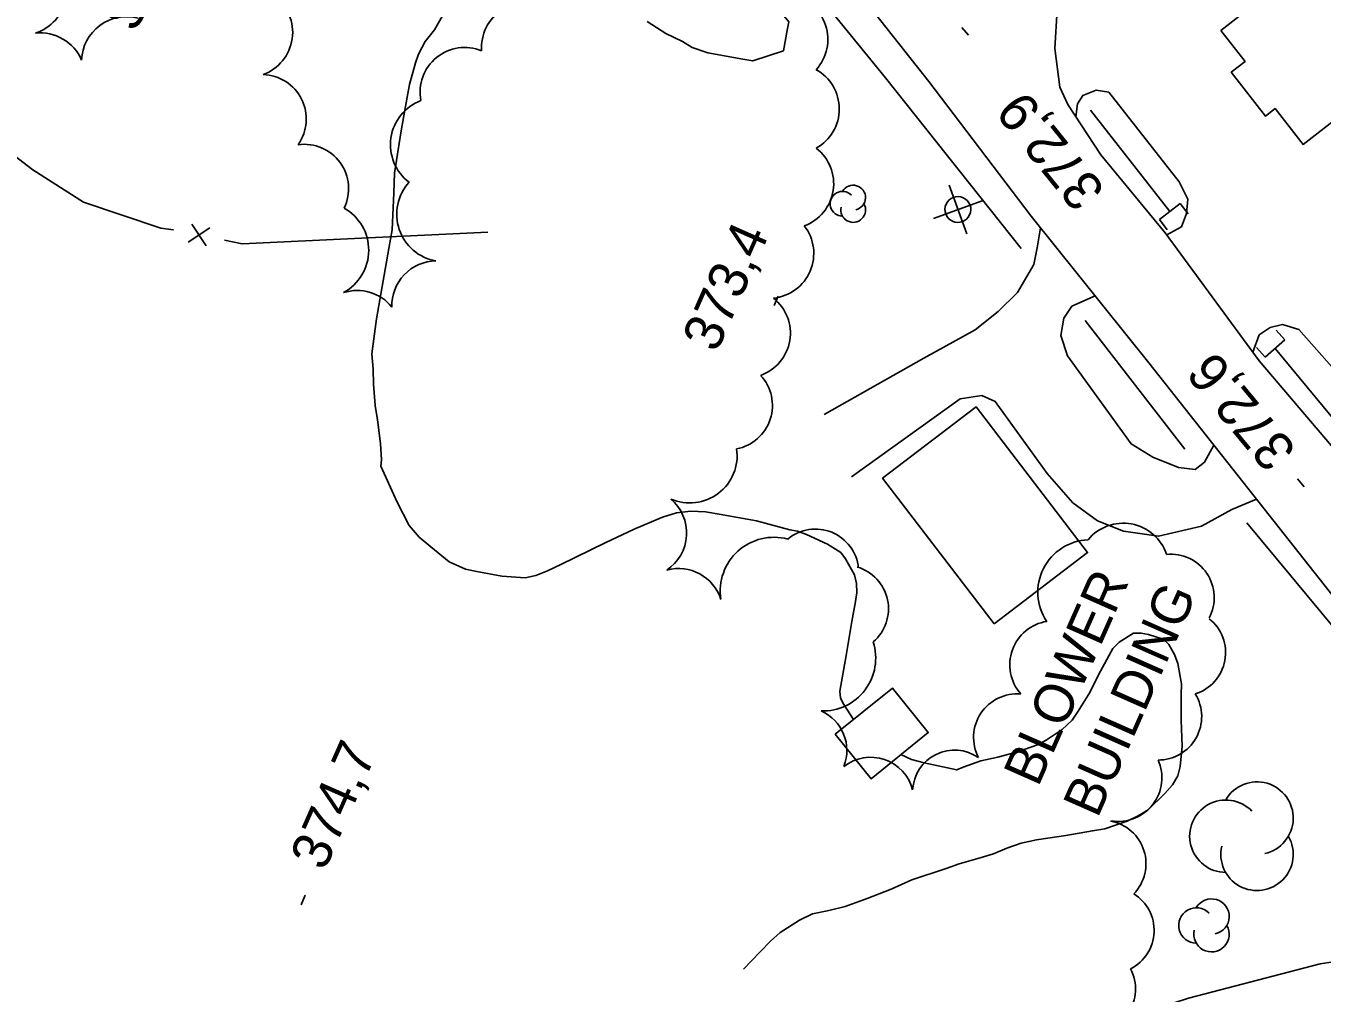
# Model space of a CAD drawing. Extents: x 287698 to 290158, y 5234163 to 5237182.
# Drawn here: x 288956.3 to 289056.1, y 5234872.4 to 5234946.9 of the extents above; entities that cross this region are included whole.
import ezdxf

# ---------------------------------------------------------------- set-up
doc = ezdxf.new("R2010")
doc.units = 0
for name, color, linetype in [('Niveau 19', 7, 'Continuous'), ('Niveau 2', 7, 'Continuous'), ('Niveau 21', 7, 'Continuous'), ('Niveau 26', 7, 'Continuous'), ('Niveau 3', 7, 'Continuous'), ('Niveau 31', 7, 'Continuous'), ('Niveau 36', 7, 'Continuous'), ('Niveau 37', 7, 'Continuous'), ('Niveau 4', 7, 'Continuous'), ('Niveau 44', 7, 'Continuous')]:
    doc.layers.add(name, color=color, linetype=linetype)

msp = doc.modelspace()

# ---------------------------------------------------------------- linework, layer by layer
at = {"layer": 'Niveau 19'}
for points in [[(289044.09, 5234930.8), (289045.22, 5234931.44), (289045.62, 5234932.45), (289045.72, 5234933.57), (289045.06, 5234934.9), (289039.63, 5234941.79), (289038.67, 5234941.96), (289037.64, 5234941.55), (289037.22, 5234940.89), (289037.09, 5234939.91)], [(289017.72, 5234916.99), (289025.38, 5234921.31), (289029.35, 5234923.51), (289031.12, 5234924.92), (289032.59, 5234926.37), (289033.87, 5234928.52), (289034.12, 5234929.82), (289034.37, 5234931.36)], [(289038.58, 5234926.11), (289036.79, 5234925.31), (289036.17, 5234924.4), (289035.93, 5234923.06), (289036.44, 5234921.49), (289041.34, 5234914.71), (289043.01, 5234913.69), (289045, 5234912.89), (289046.28, 5234912.75), (289047, 5234913.31), (289047.72, 5234914.61)], [(289059.69, 5234911.09), (289061.21, 5234912.33), (289061.52, 5234913.44), (289061.49, 5234914.76), (289060.94, 5234915.98), (289054.27, 5234923.53), (289053.01, 5234923.91), (289052.06, 5234923.68), (289051.2, 5234923.1), (289050.72, 5234921.79)], [(289051, 5234910.45), (289049.1, 5234909.65), (289046.78, 5234908.37), (289043.46, 5234907.6), (289040.75, 5234908), (289038.75, 5234908.79), (289036.87, 5234910.18), (289034.89, 5234912.44), (289030.89, 5234917.98), (289029.86, 5234918.45), (289028.19, 5234918.19), (289019.81, 5234912.17)], [(289039, 5234869.83), (289045.76, 5234872.04), (289055.91, 5234874.68), (289062.92, 5234875.75), (289066.89, 5234876.7), (289069.42, 5234877.47), (289071.11, 5234878.17), (289072.37, 5234879.23), (289073.22, 5234880.46), (289074.14, 5234881.87)]]:
    msp.add_lwpolyline(points, dxfattribs=at)
at = {"layer": 'Niveau 2'}
for points in [[(288997.13, 5234971.38), (288998.91, 5234968.79), (288999.04, 5234968.28), (288999.36, 5234967.88), (288999.63, 5234967.22), (289000.2, 5234966.21), (289000.98, 5234964.73), (289001.83, 5234963.48), (289002.39, 5234962.51), (289003.09, 5234961.52), (289004, 5234960.46), (289005.87, 5234958.04), (289007.66, 5234955.86), (289009.68, 5234953.37), (289011.15, 5234951.48), (289011.94, 5234950.63), (289014.15, 5234948.23), (289014.99, 5234947.21), (289014.9, 5234946.7), (289014.59, 5234944.99)], [(288988.34, 5234947.67), (288987.71, 5234946.6), (288987, 5234945.69), (288986.48, 5234944.72), (288986.27, 5234944.07), (288985.79, 5234942.39), (288985.62, 5234941.42), (288985.15, 5234938.81), (288984.64, 5234935.56), (288984.58, 5234934.05), (288984.46, 5234931.19), (288984.21, 5234929.75), (288983.77, 5234927.27), (288983.25, 5234924.34), (288982.9, 5234921.66), (288983, 5234920.48), (288983.02, 5234919.32), (288983.15, 5234917.67), (288983.34, 5234916.56), (288983.57, 5234914.75), (288983.65, 5234913.48), (288983.59, 5234913.01)], [(289014.59, 5234944.99), (289012.22, 5234944.21), (289011.46, 5234944.34), (289008.76, 5234944.82), (289007.55, 5234945.23), (289006.82, 5234945.71), (289005.53, 5234946.32), (289004.08, 5234947.23)], [(288983.59, 5234913.01), (288984.85, 5234910.24), (288985.77, 5234908.44), (288986.54, 5234907.53), (288987.45, 5234906.8), (288988.85, 5234905.62), (288990.11, 5234905.07), (288990.99, 5234904.88), (288992.9, 5234904.54), (288994.69, 5234904.41), (288995.51, 5234904.59), (288996.43, 5234904.95), (288997.45, 5234905.44), (289000.85, 5234907.1), (289003.08, 5234908.15), (289005.26, 5234909.08), (289006.35, 5234909.4), (289007.45, 5234909.53), (289008.58, 5234909.47), (289009.64, 5234909.3), (289012.5, 5234908.8), (289015.08, 5234908.1), (289015.67, 5234908), (289016.37, 5234907.73), (289017.97, 5234907), (289018.99, 5234906.36), (289019.37, 5234905.86), (289020.05, 5234904.63), (289020.22, 5234903.97), (289020.24, 5234903.27), (289020.14, 5234902.58), (289019.86, 5234901.04), (289019.4, 5234898.42), (289018.92, 5234895.67), (289018.98, 5234895.13), (289019.22, 5234894.64), (289019.98, 5234893.49)], [(289025.42, 5234890.15), (289027.92, 5234889.61), (289028.41, 5234889.83), (289029.79, 5234890.3), (289031.1, 5234890.59), (289032.59, 5234891), (289034.15, 5234891.54), (289034.81, 5234891.91), (289036.04, 5234892.71), (289036.8, 5234893.45), (289037.27, 5234894.14), (289038.17, 5234895.56), (289038.84, 5234896.93), (289039.94, 5234898.95), (289040.42, 5234899.45), (289041.52, 5234900.15), (289042.11, 5234900.15), (289042.7, 5234900.04), (289043.81, 5234899.67), (289044.25, 5234899.26), (289044.7, 5234898.49), (289044.94, 5234897.8), (289045.23, 5234896.23), (289045.19, 5234895.4), (289045.21, 5234893.45), (289045.28, 5234891.44), (289045.13, 5234889.87), (289044.94, 5234889.15), (289044.54, 5234888.47), (289043.95, 5234887.8), (289042.67, 5234886.54), (289041.9, 5234886.07), (289041.04, 5234885.67), (289039.33, 5234885.08), (289038.37, 5234884.93), (289036.33, 5234884.57), (289034.06, 5234884.22), (289032.88, 5234883.97), (289031.77, 5234883.59), (289030.76, 5234883.16), (289029.73, 5234882.83), (289028.11, 5234882.39), (289027.11, 5234882.02)], [(289023.63, 5234890.79), (289024.43, 5234890.41), (289025.42, 5234890.15)], [(289027.11, 5234882.02), (289024.46, 5234881.14), (289022.87, 5234880.43), (289021.02, 5234879.7), (289019.33, 5234879.1), (289018.07, 5234878.78), (289016.81, 5234878.53), (289015.81, 5234878.04), (289014.34, 5234877.08), (289013.59, 5234876.42), (289012.78, 5234875.61), (289011.52, 5234874.27)]]:
    msp.add_lwpolyline(points, dxfattribs=at)
at = {"layer": 'Niveau 21'}
for points in [[(289065.93, 5234814.28), (289080.43, 5234820.36), (289085.56, 5234822.15), (289095.57, 5234827.48), (289103.57, 5234831.83), (289105.46, 5234833.33), (289106.17, 5234834.93), (289106.24, 5234836.58), (289105.61, 5234838.24), (289104.03, 5234840.63), (289095.62, 5234852.75), (289088.9, 5234862.55), (289082.75, 5234870.74), (289074.14, 5234881.87), (289074.07, 5234881.96), (289067.25, 5234890.31), (289060.07, 5234898.99), (289052.35, 5234908.74), (289042.72, 5234920.95), (289033.65, 5234932.26), (289025.77, 5234942.63), (289016.04, 5234954.94)], [(289035.66, 5234948.13), (289035.47, 5234945.17), (289035.87, 5234942.18), (289036.47, 5234940.85), (289039.03, 5234936.97), (289043.97, 5234930.96), (289051.21, 5234921.12), (289059.26, 5234911.63), (289067.32, 5234901.46), (289070.83, 5234898.1), (289073.27, 5234896.43), (289076.14, 5234894.85), (289078.86, 5234894.47), (289081.5, 5234894.71), (289083.59, 5234895.4), (289086.13, 5234897.23), (289091.41, 5234902.88), (289091.45, 5234902.93), (289098.48, 5234911.99), (289103.98, 5234919.57), (289110.69, 5234928.93), (289116.61, 5234937.16), (289117.22, 5234937.97), (289124.9, 5234948.27)]]:
    msp.add_lwpolyline(points, dxfattribs=at)
at = {"layer": 'Niveau 26'}
for p, q in [((289043.53, 5234931.99), (289045.13, 5234933.22)), ((289045.13, 5234933.22), (289045.74, 5234932.43)), ((289043.53, 5234931.99), (289044.13, 5234931.2)), ((289053.19, 5234922.74), (289051.68, 5234921.39)), ((289053.19, 5234922.74), (289052.52, 5234923.48)), ((289051.68, 5234921.39), (289051.01, 5234922.14))]:
    msp.add_line(p, q, dxfattribs=at)
at = {"layer": 'Niveau 3'}
for p, q in [((289028.83, 5234946.19), (289028.31, 5234946.79)), ((289013.86, 5234925.37), (289014.18, 5234926.1)), ((289054.66, 5234911.41), (289054.15, 5234912.02)), ((288977.45, 5234879.23), (288977.77, 5234879.96))]:
    msp.add_line(p, q, dxfattribs=at)
at = {"layer": 'Niveau 31'}
for points in [[(289048.26, 5234946.55), (289054.75, 5234951.62), (289058.14, 5234947.28), (289060.76, 5234949.31), (289063.73, 5234945.5), (289060.76, 5234943.18), (289061.05, 5234942.81), (289054.59, 5234937.77), (289052.43, 5234940.54), (289051.69, 5234939.96), (289049.06, 5234943.33), (289050.12, 5234944.16)], [(289030.81, 5234900.85), (289022.22, 5234912.07), (289029.41, 5234917.57), (289038, 5234906.35)], [(289018.57, 5234892.35), (289022.97, 5234895.91), (289025.73, 5234892.49), (289021.33, 5234888.93)]]:
    msp.add_lwpolyline(points, close=True, dxfattribs=at)
at = {"layer": 'Niveau 36'}
for p, q in [((289028.7, 5234930.88), (289027.33, 5234934.63)), ((289029.89, 5234933.44), (289026.14, 5234932.07))]:
    msp.add_line(p, q, dxfattribs=at)
msp.add_ellipse((289028.012, 5234932.763), major_axis=(-0.907, 0.42), ratio=0.999982, dxfattribs=at)
at = {"layer": 'Niveau 37'}
for p, q in [((288948.69, 5234941.97), (288956.81, 5234935.83)), ((288970.14, 5234929.97), (288969.03, 5234931.63)), ((288968.76, 5234930.24), (288970.43, 5234931.36))]:
    msp.add_line(p, q, dxfattribs=at)
for points in [[(288956.81, 5234935.83), (288960.71, 5234933.32), (288966.65, 5234931.32), (288967.63, 5234931.19)], [(288971.55, 5234930.41), (288972.92, 5234930.13), (288991.82, 5234931.02)]]:
    msp.add_lwpolyline(points, dxfattribs=at)
at = {"layer": 'Niveau 4'}
for points in [[(288993.28, 5234980.88), (289004.62, 5234965.6), (289015.19, 5234951.84), (289022.45, 5234942.9), (289032.88, 5234929.75)], [(289038.21, 5234940.42), (289044.32, 5234932.6)], [(289037.82, 5234924.21), (289045.49, 5234914.31)], [(289052.44, 5234922.07), (289060.32, 5234912.54)], [(289050.26, 5234908.63), (289059.43, 5234897.61), (289072.56, 5234881.93)]]:
    msp.add_lwpolyline(points, dxfattribs=at)
at = {"layer": 'Niveau 44'}
for centre, radius, start, end in [((288987.977, 5234937.753), 3.645, 110.84077, 232.54268), ((288977.687, 5234934.365), 3.42, 334.14127, 97.77373), ((288988.474, 5234932.404), 3.661, 137.85158, 259.86713), ((289019.951, 5234933.682), 0.954, 282.26917, 149.72626), ((289019.131, 5234933.205), 0.954, 44.11537, 269.80396), ((289019.951, 5234932.728), 0.954, 166.93686, 29.62123), ((289013.461, 5234929.378), 3.457, 275.95745, 37.86942), ((289011.663, 5234923.242), 3.455, 289.74371, 51.36288), ((289017.039, 5234904.804), 3.349, 6.09813, 129.47002), ((289013.86, 5234903.381), 4.144, 75.33067, 188.76329), ((289038.196, 5234903.306), 4.027, 92.35548, 214.07732), ((289017.617, 5234898.216), 4.068, 268.21379, 17.80134), ((289043.438, 5234893.714), 3.344, 269.69203, 31.47496), ((289051.043, 5234885.898), 2.789, 282.26917, 149.72626), ((289048.645, 5234884.504), 2.789, 44.11537, 269.80396), ((289051.043, 5234883.11), 2.789, 166.93686, 29.62123), ((289039.821, 5234877.247), 3.302, 296.80527, 58.42284), ((289047.538, 5234878.317), 1.361, 282.26917, 149.72626), ((289046.368, 5234877.636), 1.361, 44.11537, 269.80396), ((289047.538, 5234876.956), 1.361, 166.93686, 29.62123), ((289038.294, 5234872.75), 3.391, 265.20123, 27.20434)]:
    msp.add_arc(centre, radius, start, end, dxfattribs=at)
for centre, major_axis, ratio, start_param, end_param in [((288955.929, 5234949.639), (1.757, 2.987), 0.999586, 3.984847, 6.137782), ((288973.333, 5234946.408), (0.494, 3.434), 0.999625, 3.634483, 5.790295), ((288994.764, 5234945.244), (-2.885, -1.845), 0.999862, 3.633416, 5.791362), ((289014.544, 5234945.854), (3.274, 1.111), 0.998925, 5.217696, 7.34218), ((288964.003, 5234944.16), (-2.373, -2.509), 0.999761, 3.6306, 5.438132), ((288957.371, 5234942.891), (-1.97, 2.856), 0.999759, 4.517673, 5.789132), ((288990.04, 5234941.816), (-2.65, -2.168), 0.999862, 3.634329, 5.790449), ((288974.424, 5234939.726), (-1.534, 3.063), 0.999985, 3.634366, 5.790412), ((289015.422, 5234940.507), (3.458, 0), 0.999731, 5.222352, 7.347329), ((289014.983, 5234934.751), (3.426, -0.535), 0.999978, 5.22288, 7.348687), ((288978.926, 5234929.629), (3.729, -0.029), 0.999981, 5.223602, 7.346186), ((288987.868, 5234925.372), (-1.597, -3.033), 0.999938, 3.637441, 5.232787), ((288981.773, 5234923.113), (2.472, 2.359), 0.999448, 6.196336, 7.404325), ((289010.33, 5234917.675), (3.241, -1.051), 0.999949, 5.217991, 7.343803), ((289007.371, 5234913.811), (1.633, -3.261), 0.999897, 5.406873, 7.532562), ((289003.704, 5234907.851), (3.352, 0.703), 0.999679, 5.092839, 6.947196), ((289040.74, 5234905.097), (0.64, 3.453), 0.99974, 5.218199, 7.3481), ((289044.397, 5234902.879), (0.903, 3.223), 0.99958, 4.497646, 6.654252), ((289006.507, 5234901.696), (-3.209, 1.197), 0.999938, 3.808434, 5.337363), ((289019.316, 5234902.013), (-0.699, 3.28), 0.999417, 3.637318, 5.78746), ((289035.405, 5234897.697), (-2.925, 1.727), 0.999881, 5.407038, 7.535866), ((289045.284, 5234898.643), (0.612, 3.282), 0.999213, 3.632303, 5.792475), ((289032.578, 5234892.112), (-2.797, 1.859), 0.999977, 5.217759, 7.350131), ((289016.121, 5234891.091), (-0.96, 3.21), 0.999418, 4.051794, 5.575397), ((289021.297, 5234887.25), (-3.244, 0.787), 0.999856, 3.630776, 5.613959), ((289027.757, 5234887.906), (-1.786, -2.693), 0.999994, 3.12011, 5.243858), ((289040.371, 5234888.992), (2.037, 2.655), 0.999213, 3.633775, 5.791003), ((289039.15, 5234882.388), (-1.012, 3.187), 0.999596, 3.634902, 5.789876)]:
    msp.add_ellipse(centre, major_axis=major_axis, ratio=ratio, start_param=start_param, end_param=end_param, dxfattribs=at)

# ---------------------------------------------------------------- texts
at = {"layer": 'Niveau 3'}
for s, rotation, p in [('372,9', 128.87991, (289039.45, 5234934.27)), ('373,4', 66.1217, (289009.44, 5234921.66)), ('372,6', 129.57296, (289054.18, 5234914.25)), ('374,7', 66.1217, (288979.25, 5234881.75))]:
    msp.add_text(s, height=3, rotation=rotation, dxfattribs=at).set_placement(p)
at = {"layer": 'Niveau 31'}
for s, p in [('STATION', (288964.74, 5234946.31)), ('BLOWER', (289034.18, 5234888.22)), ('BUILDING', (289038.76, 5234885.82))]:
    msp.add_text(s, height=3, rotation=66.12117, dxfattribs=at).set_placement(p)

doc.saveas('drawing.dxf')
